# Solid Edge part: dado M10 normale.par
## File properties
Title: 1320503090
Subject: Dado esagonale M10
Author: v_lucarelli
Template: RBuno.par
Last saved by: b_giovanelli
Revision: 13
Application: Solid Edge
Company: EFFEBI S.p.A.
Codice: Codice
Indice rev.: Rev.
Data rev.: Data rev.
Firma rev.: Firma rev.
Descrizione rev.: Descrizione rev.
Densità: 7860.000 kg/m^3
Precisione: 0.99
Tipo di contenuto documento: 0
Document Number: UNI 5588
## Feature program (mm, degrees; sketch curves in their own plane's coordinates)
sketch for "unnamed Protrusion 1" plane through (0, 0, 0) normal (0, 0, 1) x-axis (1, 0, 0)
extrude "unnamed Protrusion 1" add finite 8 along -normal
sketch for "Foro_1" plane through (0, 0, 0) normal (0, 0, 1) x-axis (0, 1, 0)
  hole centre (0, 0) bore radius 4.4
hole "Foro_1" nominal diameter 10 through
sketch for "unnamed RevolvedCutout 1" plane through (0, 0, 0) normal (1, 0, 0) x-axis (0, 1, 0)
revolve "unnamed RevolvedCutout 1" cut full turn 360 deg
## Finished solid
Body 1: solid body, 11 faces, 22 edges, 12 vertices.
  Faces by surface: plane 8, cone 2, cylinder 1
  Edges by curve: intersection 12, line 6, circle 4
Bounding box of the edges (mm): 17.000 x 19.630 x 8.000, from (-8.5, -9.815, -8) to (8.5, 9.815, 0).
Cylindrical faces by radius (mm): R4.4 x1
Conical faces (half-angle, radius in mm at the cone's reference point): 60 deg R0.8047 x1, 60 deg R15.3432 x1
Planar faces by outward normal: +x 1, +z 1, -x 1, -z 1, oblique 4
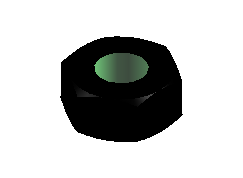
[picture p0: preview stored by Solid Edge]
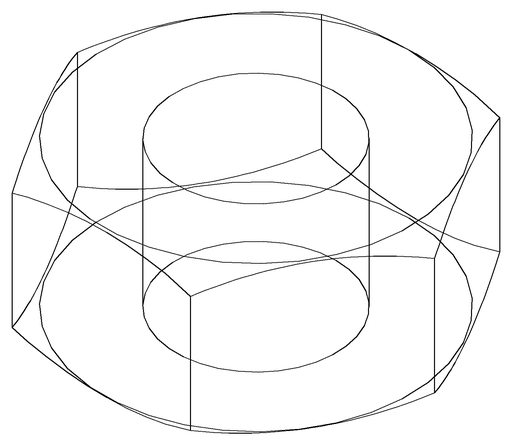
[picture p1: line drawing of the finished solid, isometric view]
